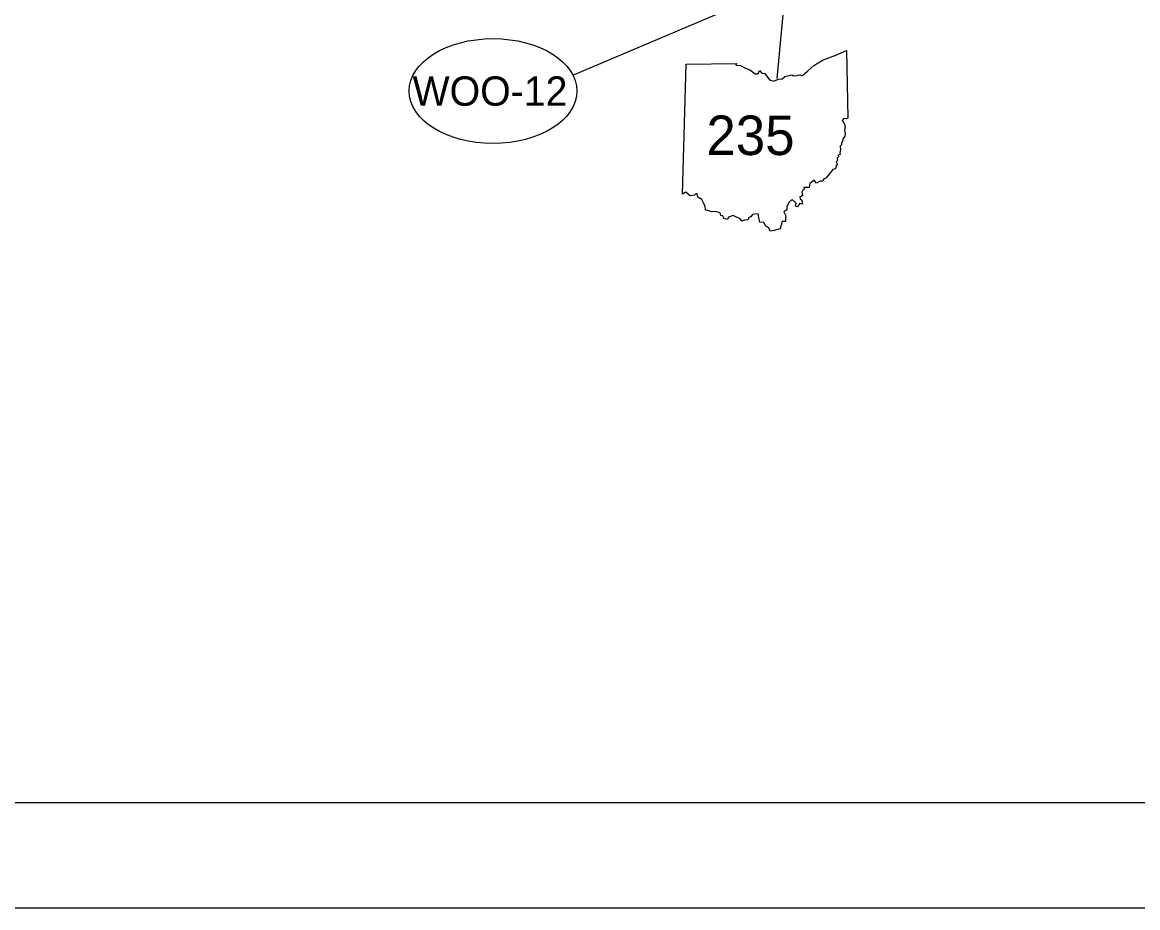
# Model space of a CAD drawing. Extents: x 0 to 851, y 0 to 440.
# Drawn here: x 176.1 to 282.5, y 0 to 84.4 of the extents above; entities that cross this region are included whole.
import ezdxf

# ---------------------------------------------------------------- set-up
doc = ezdxf.new("R2010")
doc.units = 0
for name, color, linetype in [('GM_X_State_Route', 7, 'Continuous'), ('PV_P_Text', 7, 'Continuous'), ('SH_Border', 7, 'Continuous'), ('SH_Cut_Line', 7, 'Continuous'), ('SH_Data', 7, 'Continuous')]:
    doc.layers.add(name, color=color, linetype=linetype)

msp = doc.modelspace()

# ---------------------------------------------------------------- linework, layer by layer
at = {"layer": 'GM_X_State_Route'}
msp.add_lwpolyline([(248.09, 79.05), (248.82, 86.84), (248.96, 87.39), (249.11, 88.06), (249.29, 88.82), (249.45, 89.52), (249.59, 90.14), (249.76, 90.82), (249.9, 91.43), (250.05, 92.09), (250.23, 92.85), (250.4, 93.57), (250.54, 94.16), (250.63, 94.54), (250.64, 94.64), (250.66, 94.81), (250.68, 95.06), (250.72, 95.47)], dxfattribs=at)
at = {"layer": 'PV_P_Text'}
msp.add_line((239.07, 68.03), (239.41, 80.4), dxfattribs=at)
msp.add_line((239.07, 68.03), (239.41, 80.4), dxfattribs=at)
for points in [[(239.41, 80.4), (244.22, 80.48), (244.14, 80.33), (244.59, 80.3), (245.07, 80.04), (245.48, 79.87), (245.98, 79.48), (246.28, 79.48), (246.4, 79.8), (246.63, 79.55), (246.9, 79.51), (247.37, 78.92), (247.76, 78.79), (248.22, 78.99), (248.56, 79.02), (248.82, 79.23), (249.48, 79.4), (249.66, 79.29), (250.01, 79.32), (250.18, 79.39), (250.49, 79.32), (251.02, 79.77), (251.57, 80.3), (252.42, 80.8), (253.69, 81.28), (254.69, 81.7), (254.83, 75.28)], [(239.41, 80.4), (244.22, 80.48), (244.14, 80.33), (244.59, 80.3), (245.07, 80.04), (245.48, 79.87), (245.98, 79.48), (246.28, 79.48), (246.4, 79.8), (246.63, 79.55), (246.9, 79.51), (247.37, 78.92), (247.76, 78.79), (248.22, 78.99), (248.56, 79.02), (248.82, 79.23), (249.48, 79.4), (249.66, 79.29), (250.01, 79.32), (250.18, 79.39), (250.49, 79.32), (251.02, 79.77), (251.57, 80.3), (252.42, 80.8), (253.69, 81.28), (254.69, 81.7), (254.83, 75.28)], [(254.83, 75.28), (254.69, 75.19), (254.46, 75.23), (254.3, 75.05), (254.49, 74.75), (254.58, 74.44), (254.5, 74.09), (254.58, 73.8), (254.53, 73.56), (254.38, 73.32), (254.33, 73.09), (254.21, 72.84), (254.22, 72.71), (254.1, 72.6), (254.13, 72.2), (254.07, 71.98), (254.09, 71.79), (253.9, 71.74), (253.94, 71.58), (253.82, 71.46), (253.85, 71.24), (253.71, 71.11), (253.84, 70.84), (253.73, 70.76), (253.65, 70.43), (253.4, 70.36), (252.91, 69.76), (252.74, 69.54), (252.55, 69.48), (252.44, 69.25), (252.2, 69.25), (251.84, 69.08), (251.61, 69.36), (251.2, 69.03), (251.15, 68.64), (250.64, 68.65), (250.66, 68.46), (250.54, 68.4), (250.44, 68.21), (250.5, 67.86), (250.26, 67.77), (250.29, 67.57), (250.44, 67.45), (250.51, 67.06), (250.25, 67.14), (250.04, 66.81), (249.83, 66.89), (249.9, 67.17), (249.53, 67.5), (249.19, 67.23), (249, 66.81), (249, 66.52), (248.74, 66.35), (248.91, 65.95), (248.88, 65.67), (248.88, 65.41), (248.56, 65.42), (248.37, 64.71)], [(254.83, 75.28), (254.69, 75.19), (254.46, 75.23), (254.3, 75.05), (254.49, 74.75), (254.58, 74.44), (254.5, 74.09), (254.58, 73.8), (254.53, 73.56), (254.38, 73.32), (254.33, 73.09), (254.21, 72.84), (254.22, 72.71), (254.1, 72.6), (254.13, 72.2), (254.07, 71.98), (254.09, 71.79), (253.9, 71.74), (253.94, 71.58), (253.82, 71.46), (253.85, 71.24), (253.71, 71.11), (253.84, 70.84), (253.73, 70.76), (253.65, 70.43), (253.4, 70.36), (252.91, 69.76), (252.74, 69.54), (252.55, 69.48), (252.44, 69.25), (252.2, 69.25), (251.84, 69.08), (251.61, 69.36), (251.2, 69.03), (251.15, 68.64), (250.64, 68.65), (250.66, 68.46), (250.54, 68.4), (250.44, 68.21), (250.5, 67.86), (250.26, 67.77), (250.29, 67.57), (250.44, 67.45), (250.51, 67.06), (250.25, 67.14), (250.04, 66.81), (249.83, 66.89), (249.9, 67.17), (249.53, 67.5), (249.19, 67.23), (249, 66.81), (249, 66.52), (248.74, 66.35), (248.91, 65.95), (248.88, 65.67), (248.88, 65.41), (248.56, 65.42), (248.37, 64.71)], [(248.37, 64.71), (247.81, 64.57), (247.42, 64.49), (247.28, 64.81), (247, 64.98), (246.82, 65.31), (246.42, 65.35), (246.33, 65.8), (246.28, 66.16), (245.74, 66.07), (245.59, 65.85), (245.39, 65.79), (245.28, 65.57), (245.02, 65.55), (244.73, 65.44), (244.55, 65.66), (244.08, 65.88), (243.88, 66), (243.44, 65.82), (243.35, 65.61), (243, 65.7), (242.92, 65.94), (242.71, 66), (242.66, 66.25), (242.21, 66.38), (241.87, 66.33), (241.26, 66.53), (241.23, 66.85), (241.02, 67.25), (240.91, 67.52), (240.53, 67.73), (240.45, 68.06), (240.33, 68.05), (240.22, 67.92), (239.79, 67.86), (239.62, 67.99), (239.38, 68.22), (239.07, 68.03)], [(248.37, 64.71), (247.81, 64.57), (247.42, 64.49), (247.28, 64.81), (247, 64.98), (246.82, 65.31), (246.42, 65.35), (246.33, 65.8), (246.28, 66.16), (245.74, 66.07), (245.59, 65.85), (245.39, 65.79), (245.28, 65.57), (245.02, 65.55), (244.73, 65.44), (244.55, 65.66), (244.08, 65.88), (243.88, 66), (243.44, 65.82), (243.35, 65.61), (243, 65.7), (242.92, 65.94), (242.71, 66), (242.66, 66.25), (242.21, 66.38), (241.87, 66.33), (241.26, 66.53), (241.23, 66.85), (241.02, 67.25), (240.91, 67.52), (240.53, 67.73), (240.45, 68.06), (240.33, 68.05), (240.22, 67.92), (239.79, 67.86), (239.62, 67.99), (239.38, 68.22), (239.07, 68.03)]]:
    msp.add_lwpolyline(points, dxfattribs=at)
at = {"layer": 'SH_Border'}
msp.add_lwpolyline([(30, 430), (670, 430), (670, 10), (30, 10)], close=True, dxfattribs=at)
at = {"layer": 'SH_Cut_Line'}
msp.add_lwpolyline([(0, 0), (680, 0), (680, 440), (0, 440)], close=True, dxfattribs=at)
at = {"layer": 'SH_Data'}
msp.add_line((228.61, 79.37), (249.11, 88.06), dxfattribs=at)
msp.add_ellipse((220.99, 77.85), major_axis=(8, 0), ratio=0.625, dxfattribs=at)

# ---------------------------------------------------------------- texts
at = {"layer": 'PV_P_Text'}
msp.add_text('235', height=3.769, dxfattribs=at).set_placement((241.34, 71.75))
at = {"layer": 'SH_Data'}
msp.add_text('WOO-12', height=2.8, dxfattribs=at).set_placement((213.32, 76.45))

doc.saveas('drawing.dxf')
